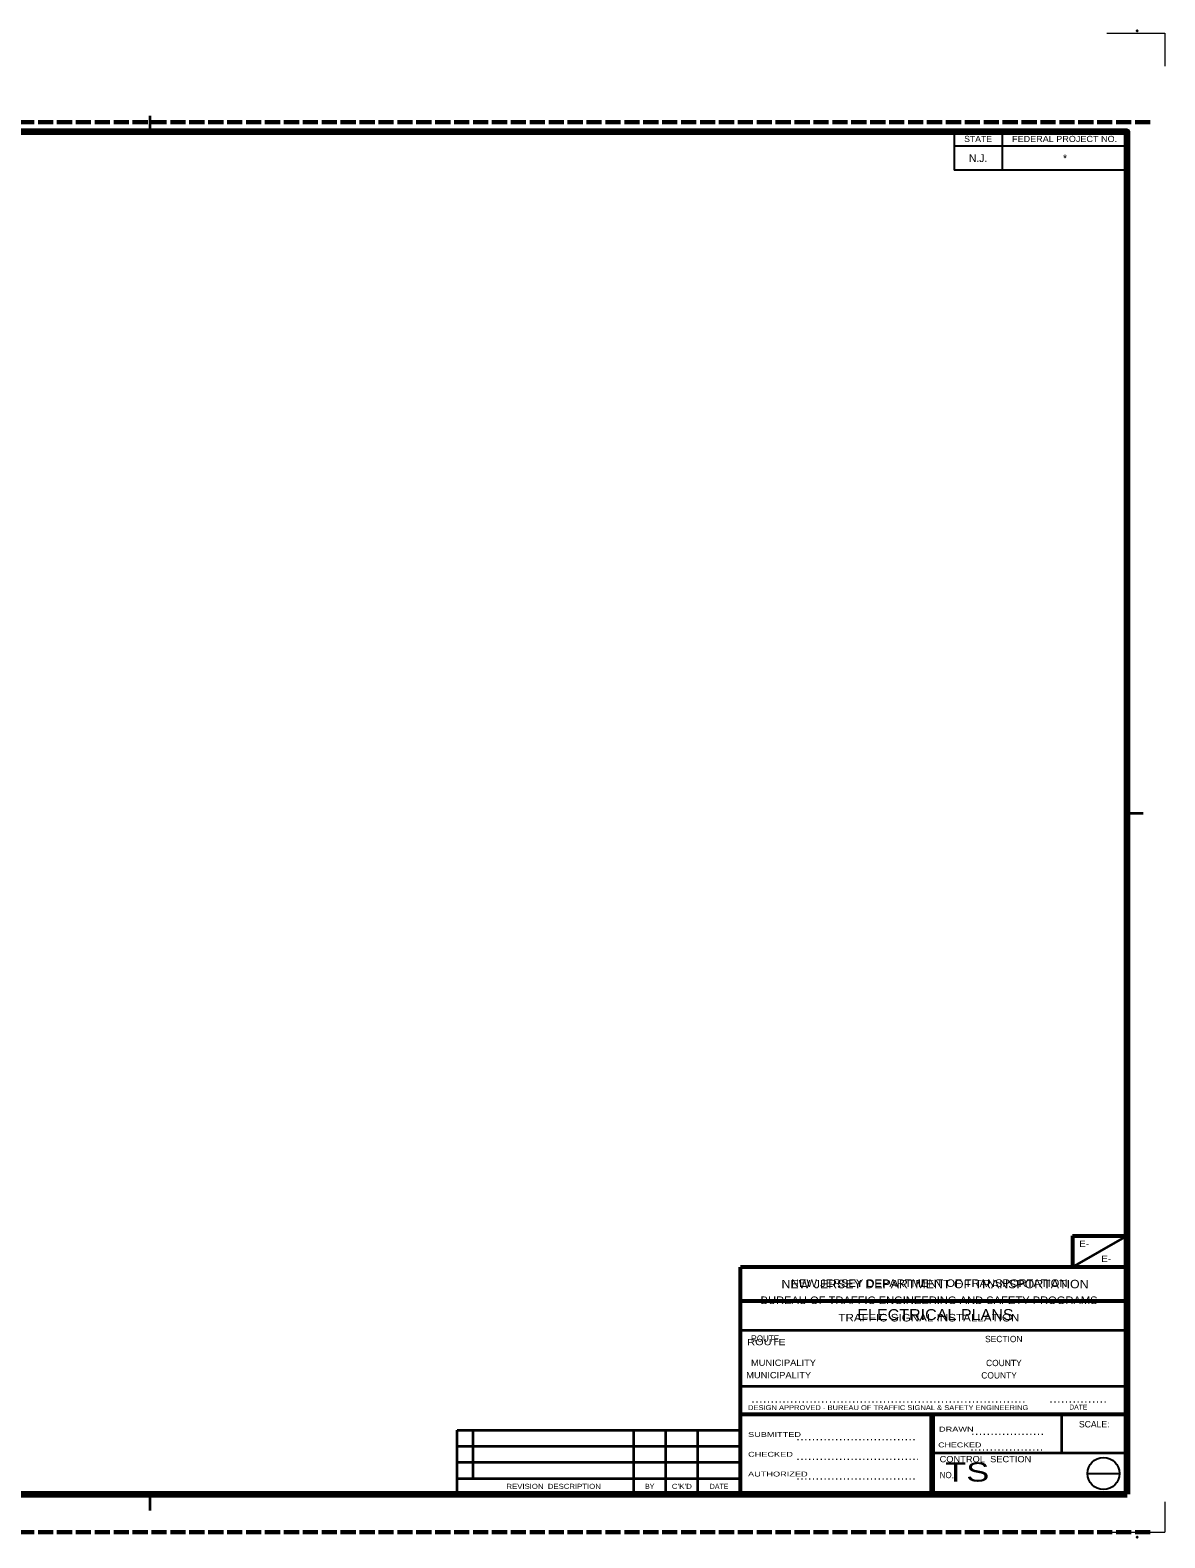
# Model space of a CAD drawing. Extents: x 214293 to 215244, y 214345 to 214808.
# Drawn here: x 215108.8 to 215243.8, y 214617.5 to 214796.7 of the extents above; entities that cross this region are included whole.
import ezdxf
from ezdxf.enums import TextEntityAlignment as Align

# ---------------------------------------------------------------- set-up
doc = ezdxf.new("R2010")
doc.units = 0
doc.header["$LTSCALE"] = 0.3
doc.header["$PDMODE"] = 32
doc.header["$PDSIZE"] = 0.15
doc.linetypes.add('DOTTED', pattern=[1.5, 0.3, -1.2])
doc.linetypes.add('LONG_DASHED', pattern=[7.5, 6, -1.5])
for name, color, linetype, lineweight in [('1', 7, 'Continuous', 25), ('25', 7, 'Continuous', 35), ('27', 7, 'Continuous', 35)]:
    doc.layers.add(name, color=color, linetype=linetype, lineweight=lineweight)

msp = doc.modelspace()

# ---------------------------------------------------------------- linework, layer by layer
at = {"layer": '1', "lineweight": 35}
for p, q in [((215123.0344, 214786.5468), (215123.0344, 214784.6568)), ((215239.2844, 214703.6568), (215241.2044, 214703.6568)), ((215123.0344, 214622.6568), (215123.0344, 214620.7368))]:
    msp.add_line(p, q, dxfattribs=at)
at = {"layer": '1', "linetype": 'LONG_DASHED', "lineweight": 60}
for p, q in [((215242.0344, 214785.7968), (214973.8104, 214785.7968)), ((215242.0344, 214618.1568), (214973.8104, 214618.1568))]:
    msp.add_line(p, q, dxfattribs=at)
at = {"layer": '1'}
for p, q in [((215218.7104, 214784.6568), (215218.7104, 214780.0848)), ((215224.4254, 214784.6568), (215224.4254, 214780.0848)), ((215239.2844, 214782.9423), (215218.7104, 214782.9423)), ((215239.2844, 214780.0848), (215218.7104, 214780.0848))]:
    msp.add_line(p, q, dxfattribs=at)
at = {"layer": '1', "lineweight": 13}
for p in [(215243.7844, 214621.7568), (215236.8844, 214618.1568)]:
    msp.add_line(p, (215243.7844, 214618.1568), dxfattribs=at)
msp.add_lwpolyline([(215236.8844, 214796.3568), (215243.7844, 214796.3568), (215243.7844, 214792.4568)], dxfattribs=at)
at = {"layer": '1', "lineweight": 158}
msp.add_lwpolyline([(215239.2844, 214622.6568), (215239.2844, 214784.6568), (215006.7844, 214784.6568), (215006.7844, 214622.6568)], close=True, dxfattribs=at)
at = {"layer": '1'}
for p in [(215240.4844, 214796.6568), (215240.4844, 214617.5568)]:
    msp.add_point(p, dxfattribs=at)
at = {"layer": '25'}
msp.add_line((215232.7844, 214649.6568), (215239.2844, 214653.4068), dxfattribs=at)
at = {"layer": '25', "lineweight": 53}
for p, q in [((215232.7844, 214653.4068), (215239.2844, 214653.4068)), ((215232.7844, 214653.4068), (215232.7844, 214649.6568)), ((215193.2844, 214622.6568), (215193.2844, 214649.6568)), ((215239.2844, 214649.6568), (215193.2844, 214649.6568)), ((215193.2844, 214645.6568), (215239.2844, 214645.6568)), ((215239.2844, 214632.1368), (215193.2844, 214632.1368)), ((215216.1844, 214632.1368), (215216.1844, 214622.6568))]:
    msp.add_line(p, q, dxfattribs=at)
at = {"layer": '25', "lineweight": 25}
msp.add_line((215234.5744, 214625.1468), (215238.3844, 214625.1468), dxfattribs=at)
msp.add_circle((215236.4852, 214625.133), 1.9049, dxfattribs=at)
at = {"layer": '27', "lineweight": 53}
for p in [(215193.2844, 214622.6568), (215239.2844, 214649.6568)]:
    msp.add_line(p, (215193.2844, 214649.6568), dxfattribs=at)
at = {"layer": '27'}
for p, q in [((215239.2844, 214642.1268), (215193.2844, 214642.1268)), ((215239.2844, 214635.4668), (215193.2844, 214635.4668)), ((215215.9444, 214622.9568), (215215.9444, 214632.1968)), ((215239.2844, 214632.1368), (215193.2844, 214632.1368)), ((215231.5144, 214627.5468), (215231.5144, 214632.1368)), ((215159.5944, 214630.2768), (215193.2844, 214630.2768)), ((215159.5944, 214622.6568), (215159.5944, 214630.2768)), ((215161.5144, 214624.5468), (215161.5144, 214630.2768)), ((215180.5944, 214622.6568), (215180.5944, 214630.2768)), ((215184.4044, 214622.6568), (215184.4044, 214630.2768)), ((215188.2144, 214622.6568), (215188.2144, 214630.2768)), ((215159.5944, 214628.3868), (215193.2844, 214628.3868)), ((215239.2844, 214627.5468), (215215.9444, 214627.5468)), ((215159.5944, 214626.4668), (215193.2844, 214626.4668)), ((215159.5944, 214624.5468), (215193.2844, 214624.5468))]:
    msp.add_line(p, q, dxfattribs=at)
at = {"layer": '27', "linetype": 'DOTTED', "lineweight": 13}
for p, q in [((215194.7492, 214633.647), (215227.1293, 214633.647)), ((215230.1954, 214633.647), (215236.7824, 214633.647)), ((215200.0989, 214629.189), (215214.3556, 214629.189)), ((215200.0989, 214629.189), (215214.3556, 214629.189)), ((215220.8847, 214629.8221), (215229.3641, 214629.8221)), ((215200.0989, 214626.8326), (215214.4011, 214626.8326)), ((215200.0989, 214626.8326), (215214.4011, 214626.8326)), ((215220.7846, 214627.9479), (215229.2641, 214627.9479)), ((215200.0989, 214624.4853), (215214.3556, 214624.4853))]:
    msp.add_line(p, q, dxfattribs=at)

# ---------------------------------------------------------------- texts
at = {"layer": '1'}
for s, width, p in [('STATE', 1.05, (215221.5679, 214783.4338)), ('FEDERAL PROJECT NO.', 1.1, (215231.8549, 214783.4338))]:
    msp.add_text(s, height=0.7315, dxfattribs=dict(at, width=width)).set_placement(p, align=Align.CENTER)
for s, p in [('N.J.', (215221.5679, 214781.0563)), ('*', (215231.9039, 214781.0478))]:
    msp.add_text(s, height=0.9144, dxfattribs=at).set_placement(p, align=Align.CENTER)
at = {"layer": '25'}
for s, height, width, p in [('E-   ', 0.75, 1.15, (215234.6635, 214652.0608)), ('E-   ', 0.75, 1.15, (215237.2829, 214650.2714)), ('NEW JERSEY DEPARTMENT OF TRANSPORTATION', 1, 1.1, (215216.4419, 214647.1568)), ('ELECTRICAL PLANS', 1.3, 1.1, (215216.4891, 214643.3735)), ('CONTROL  SECTION', 0.75, 1.1, (215222.4432, 214626.4668)), ('NO.', 0.75, 0.95, (215217.845, 214624.5768))]:
    msp.add_text(s, height=height, dxfattribs=dict(at, width=width)).set_placement(p, align=Align.CENTER)
for s, width, p in [('ROUTE', 0.95, (215194.5544, 214640.8068)), ('MUNICIPALITY', 1.1, (215194.5544, 214637.9268))]:
    msp.add_text(s, height=0.75, dxfattribs=dict(at, width=width)).set_placement(p)
for s, p in [('SECTION', (215222.3944, 214640.7468)), ('COUNTY', (215222.5144, 214637.8968))]:
    msp.add_text(s, height=0.75, dxfattribs=at).set_placement(p)
at = {"layer": '27'}
for s, height, width, p in [('NEW JERSEY DEPARTMENT OF TRANSPORTATION', 0.9, 1.1, (215215.7528, 214647.3168)), ('BUREAU OF TRAFFIC ENGINEERING AND SAFETY PROGRAMS', 0.9, 1.1, (215215.735, 214645.2768)), ('TRAFFIC SIGNAL INSTALLATION', 0.9, 1.15, (215215.7106, 214643.2068)), ('REVISION  DESCRIPTION', 0.6, 1.15, (215171.0732, 214623.3048)), ('BY', 0.6, 0.9, (215182.5022, 214623.3048)), ("C'K'D", 0.6, 1.2, (215186.3262, 214623.3048))]:
    msp.add_text(s, height=height, dxfattribs=dict(at, width=width)).set_placement(p, align=Align.CENTER)
for s, height, width, p in [('ROUTE                                                         ', 0.75, 1.3, (215194.1044, 214640.3868)), ('MUNICIPALITY', 0.75, 1.1, (215193.9844, 214636.4568)), ('DESIGN APPROVED - BUREAU OF TRAFFIC SIGNAL & SAFETY ENGINEERING', 0.5823, 1.15, (215194.2033, 214632.6735)), ('DRAWN                     ', 0.5822, 1.4, (215216.9179, 214630.1133)), ('SUBMITTED                        ', 0.5823, 1.4, (215194.2033, 214629.4801)), ('CHECKED                  ', 0.5822, 1.35, (215216.8179, 214628.2391)), ('CHECKED                          ', 0.5823, 1.4, (215194.2033, 214627.1237)), ('AUTHORIZED                       ', 0.5823, 1.4, (215194.2033, 214624.7764)), ('TS     ', 2.275, 1.35, (215217.6458, 214624.1714))]:
    msp.add_text(s, height=height, dxfattribs=dict(at, width=width)).set_placement(p)
msp.add_text('COUNTY', height=0.75, dxfattribs=at).set_placement((215221.9444, 214636.4268))
for s, height, p in [('DATE', 0.5823, (215233.4889, 214632.7372)), ('SCALE:', 0.7642, (215235.3811, 214630.6083)), ('DATE', 0.6, (215190.7577, 214623.3048))]:
    msp.add_text(s, height=height, dxfattribs=at).set_placement(p, align=Align.CENTER)

doc.saveas('drawing.dxf')
